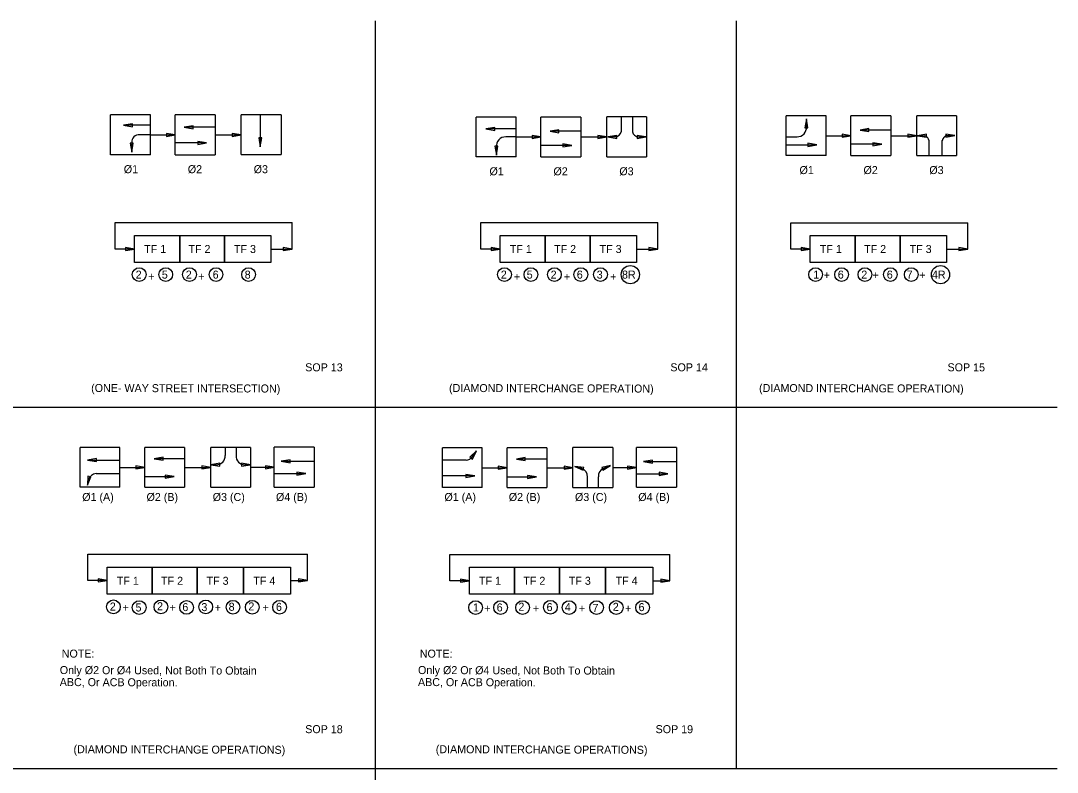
# Model space of a CAD drawing. Extents: x 10027 to 10797, y 10033 to 10528.
# Drawn here: x 10344.3 to 10797.5, y 10199.9 to 10528.4 of the extents above; entities that cross this region are included whole.
import ezdxf

# ---------------------------------------------------------------- set-up
doc = ezdxf.new("R2010")
doc.units = 0
for name, color, linetype in [('AdhocPoint_dp', 7, 'Continuous'), ('Default', 7, 'Continuous'), ('Dimension', 7, 'Continuous'), ('DSIndex', 7, 'Continuous'), ('SupstrConc', 7, 'Continuous')]:
    doc.layers.add(name, color=color, linetype=linetype)

msp = doc.modelspace()

# ---------------------------------------------------------------- linework, layer by layer
at = {"layer": 'AdhocPoint_dp'}
for p, q in [((10499.47, 10033.43), (10499.47, 10528.43)), ((10657.28, 10201.33), (10657.28, 10528.43)), ((10027.5, 10359.54), (10797.5, 10359.54)), ((10797.5, 10201.33), (10027.5, 10201.33))]:
    msp.add_line(p, q, dxfattribs=at)
at = {"layer": 'Default'}
for p, q in [((10401.03, 10487.23), (10383.63, 10487.23)), ((10383.63, 10469.84), (10383.63, 10487.23)), ((10401.03, 10469.84), (10401.03, 10487.23)), ((10411.92, 10469.84), (10411.92, 10487.23)), ((10429.32, 10487.23), (10411.92, 10487.23)), ((10429.32, 10487.23), (10429.32, 10469.84)), ((10440.72, 10469.91), (10440.72, 10487.31)), ((10458.12, 10487.31), (10440.72, 10487.31)), ((10449.05, 10487.02), (10449.05, 10473.3)), ((10458.12, 10487.31), (10458.12, 10469.91)), ((10696.42, 10486.84), (10679.03, 10486.84)), ((10679.03, 10469.45), (10679.03, 10486.84)), ((10696.42, 10469.45), (10696.42, 10486.84)), ((10707.31, 10469.45), (10707.31, 10486.84)), ((10724.71, 10486.84), (10707.31, 10486.84)), ((10724.71, 10486.84), (10724.71, 10469.45)), ((10736.12, 10469.52), (10736.12, 10486.92)), ((10753.51, 10486.92), (10736.12, 10486.92)), ((10753.51, 10486.92), (10753.51, 10469.52)), ((10401.03, 10482.74), (10389.23, 10482.74)), ((10429.16, 10481.87), (10415.83, 10481.87)), ((10560.88, 10486.31), (10543.49, 10486.31)), ((10543.49, 10468.92), (10543.49, 10486.31)), ((10560.88, 10468.92), (10560.88, 10486.31)), ((10571.77, 10468.92), (10571.77, 10486.31)), ((10589.17, 10486.31), (10571.77, 10486.31)), ((10589.17, 10486.31), (10589.17, 10468.92)), ((10600.58, 10468.99), (10600.58, 10486.39)), ((10617.97, 10486.39), (10600.58, 10486.39)), ((10606.81, 10486.39), (10606.81, 10479.91)), ((10611.8, 10486.39), (10611.8, 10479.91)), ((10617.97, 10486.39), (10617.97, 10468.99)), ((10687.83, 10482.09), (10687.83, 10485.54)), ((10401.03, 10478.54), (10396.28, 10478.54)), ((10401.03, 10478.54), (10411.92, 10478.54)), ((10429.32, 10478.54), (10440.72, 10478.54)), ((10560.88, 10481.15), (10547.72, 10481.15)), ((10561.1, 10477.61), (10556.39, 10477.61)), ((10560.88, 10477.61), (10571.77, 10477.61)), ((10589.17, 10480.1), (10575.73, 10480.1)), ((10589.17, 10477.61), (10600.58, 10477.61)), ((10679.03, 10477.71), (10683.73, 10477.71)), ((10696.42, 10478.14), (10707.31, 10478.14)), ((10724.71, 10480.63), (10711.27, 10480.63)), ((10724.71, 10478.14), (10736.12, 10478.14)), ((10392.85, 10475.3), (10392.85, 10470.96)), ((10425.61, 10474.98), (10412.02, 10474.98)), ((10552.3, 10473.24), (10552.3, 10469.68)), ((10585.26, 10473.93), (10571.77, 10473.93)), ((10679.07, 10474.17), (10692.4, 10474.17)), ((10720.8, 10474.46), (10707.31, 10474.46)), ((10741.51, 10469.52), (10741.51, 10476)), ((10747.14, 10469.52), (10747.14, 10476)), ((10401.03, 10469.84), (10383.63, 10469.84)), ((10411.92, 10469.84), (10429.32, 10469.84)), ((10440.72, 10469.91), (10458.12, 10469.91)), ((10560.88, 10468.92), (10543.49, 10468.92)), ((10571.77, 10468.92), (10589.17, 10468.92)), ((10600.58, 10468.99), (10617.97, 10468.99)), ((10696.42, 10469.45), (10679.03, 10469.45)), ((10707.31, 10469.45), (10724.71, 10469.45)), ((10736.12, 10469.52), (10753.51, 10469.52)), ((10385.58, 10440.15), (10462.98, 10440.15)), ((10385.58, 10428.63), (10385.58, 10440.15)), ((10462.98, 10428.63), (10462.98, 10440.15)), ((10545.43, 10440.15), (10622.83, 10440.15)), ((10545.43, 10428.63), (10545.43, 10440.15)), ((10622.83, 10428.63), (10622.83, 10440.15)), ((10680.97, 10440.1), (10758.37, 10440.1)), ((10680.97, 10428.58), (10680.97, 10440.1)), ((10758.37, 10428.58), (10758.37, 10440.1)), ((10394.07, 10428.63), (10385.58, 10428.63)), ((10453.61, 10428.63), (10462.98, 10428.63)), ((10553.93, 10428.63), (10545.43, 10428.63)), ((10613.47, 10428.63), (10622.83, 10428.63)), ((10689.47, 10428.58), (10680.97, 10428.58)), ((10749.01, 10428.58), (10758.37, 10428.58)), ((10387.7, 10341.85), (10370.31, 10341.85)), ((10370.31, 10324.46), (10370.31, 10341.85)), ((10387.7, 10324.46), (10387.7, 10341.85)), ((10398.6, 10324.46), (10398.6, 10341.85)), ((10415.99, 10341.85), (10398.6, 10341.85)), ((10415.99, 10341.85), (10415.99, 10324.46)), ((10427.4, 10324.53), (10427.4, 10341.93)), ((10444.8, 10341.93), (10427.4, 10341.93)), ((10433.7, 10341.95), (10433.7, 10338.36)), ((10438.5, 10341.95), (10438.5, 10338.36)), ((10444.8, 10341.93), (10444.8, 10324.53)), ((10455.2, 10324.58), (10455.2, 10341.98)), ((10472.59, 10341.98), (10455.2, 10341.98)), ((10472.59, 10341.98), (10472.59, 10324.58)), ((10546.08, 10341.72), (10528.68, 10341.72)), ((10528.68, 10324.32), (10528.68, 10341.72)), ((10546.08, 10324.32), (10546.08, 10341.72)), ((10556.97, 10324.32), (10556.97, 10341.72)), ((10574.37, 10341.72), (10556.97, 10341.72)), ((10574.37, 10341.72), (10574.37, 10324.32)), ((10585.77, 10324.4), (10585.77, 10341.79)), ((10603.17, 10341.79), (10585.77, 10341.79)), ((10603.17, 10341.79), (10603.17, 10324.4)), ((10613.57, 10324.45), (10613.57, 10341.85)), ((10630.97, 10341.85), (10613.57, 10341.85)), ((10630.97, 10341.85), (10630.97, 10324.45)), ((10415.97, 10336.95), (10402.63, 10336.95)), ((10541.85, 10337.98), (10543.57, 10340.36)), ((10373.56, 10336.33), (10387.7, 10336.33)), ((10387.7, 10333.15), (10398.6, 10333.15)), ((10415.99, 10333.15), (10427.4, 10333.15)), ((10429.76, 10334.34), (10427.4, 10334.34)), ((10442.43, 10334.34), (10444.8, 10334.34)), ((10444.8, 10333.23), (10455.2, 10333.23)), ((10458.26, 10335.85), (10472.59, 10335.85)), ((10539.02, 10336.25), (10528.68, 10336.25)), ((10546.08, 10333.02), (10556.97, 10333.02)), ((10574.34, 10336.82), (10561.01, 10336.82)), ((10574.37, 10333.02), (10585.77, 10333.02)), ((10603.17, 10333.1), (10613.57, 10333.1)), ((10616.63, 10335.72), (10630.97, 10335.72)), ((10377.36, 10330.54), (10387.7, 10330.54)), ((10398.6, 10329.12), (10411.41, 10329.12)), ((10455.2, 10330.48), (10468.92, 10330.48)), ((10542.82, 10329.46), (10528.68, 10329.46)), ((10556.97, 10328.99), (10569.78, 10328.99)), ((10592.08, 10324.4), (10592.08, 10328.93)), ((10596.87, 10324.4), (10596.87, 10329.08)), ((10613.57, 10330.35), (10627.3, 10330.35)), ((10387.7, 10324.46), (10370.31, 10324.46)), ((10398.6, 10324.46), (10415.99, 10324.46)), ((10427.4, 10324.53), (10444.8, 10324.53)), ((10455.2, 10324.58), (10472.59, 10324.58)), ((10546.08, 10324.32), (10528.68, 10324.32)), ((10556.97, 10324.32), (10574.37, 10324.32)), ((10585.77, 10324.4), (10603.17, 10324.4)), ((10613.57, 10324.45), (10630.97, 10324.45)), ((10373.61, 10295.24), (10469.67, 10295.24)), ((10373.61, 10283.72), (10373.61, 10295.24)), ((10469.67, 10283.72), (10469.67, 10295.24)), ((10531.98, 10295.11), (10628.05, 10295.11)), ((10531.98, 10283.59), (10531.98, 10295.11)), ((10628.05, 10283.59), (10628.05, 10295.11)), ((10382.1, 10283.72), (10373.61, 10283.72)), ((10462.24, 10283.72), (10469.67, 10283.72)), ((10540.48, 10283.59), (10531.98, 10283.59)), ((10620.61, 10283.59), (10628.05, 10283.59))]:
    msp.add_line(p, q, dxfattribs=at)
for centre in [(10384.84, 10272.19), (10396.12, 10271.87), (10405.6, 10272.14), (10416.85, 10271.95), (10425.22, 10272.17), (10437.13, 10272.04), (10445.53, 10272.03), (10457.49, 10272.03), (10543.17, 10271.86), (10554.12, 10271.86), (10563.74, 10271.86), (10575.88, 10272.02), (10584.09, 10271.86), (10596.12, 10271.86), (10604.69, 10271.9), (10616.18, 10271.86)]:
    msp.add_circle(centre, 3, dxfattribs=at)
for centre, radius, start, end in [((10683.87, 10481.69), 3.98, 268.0112, 5.8153), ((10396.06, 10475.33), 3.21, 86.1951, 181.3491), ((10556.25, 10473.64), 3.98, 88.0112, 185.8153), ((10603.91, 10480.57), 2.97, 280.5531, 347.2625), ((10614.7, 10480.57), 2.97, 192.7375, 264.4319), ((10738.62, 10475.34), 2.97, 12.7375, 69.8753), ((10750.03, 10475.34), 2.97, 104.651, 167.2625), ((10429.93, 10338.12), 3.78, 267.4678, 3.6758), ((10442.27, 10338.12), 3.78, 176.3242, 272.5322), ((10538.63, 10340.06), 3.83, 275.8582, 327.0511), ((10588.31, 10329.17), 3.78, 356.3242, 69.2644), ((10600.64, 10329.32), 3.78, 116.8576, 183.6758), ((10377.75, 10326.73), 3.83, 95.8582, 167.523)]:
    msp.add_arc(centre, radius, start, end, dxfattribs=at)
at = {"layer": 'Dimension'}
for p, q in [((10604.45, 10477.64), (10600.99, 10477.64)), ((10614.41, 10477.61), (10617.66, 10477.61)), ((10736.42, 10478.13), (10739.64, 10478.13)), ((10749.28, 10478.22), (10752.66, 10478.22)), ((10589.64, 10332.71), (10586.6, 10333.49)), ((10598.93, 10332.69), (10602.22, 10333.96)), ((10374.01, 10327.56), (10373.59, 10325.32))]:
    msp.add_line(p, q, dxfattribs=at)
for centre, radius in [((10396.12, 10417.44), 3), ((10407.75, 10417.44), 3), ((10418.12, 10417.44), 3), ((10429.7, 10417.44), 3), ((10443.94, 10417.44), 3), ((10555.82, 10417.44), 3), ((10567.36, 10417.44), 3), ((10577.64, 10417.44), 3), ((10589.2, 10417.44), 3), ((10597.79, 10417.44), 3), ((10610.85, 10417.44), 3.99), ((10691.84, 10417.44), 3), ((10703.21, 10417.44), 3), ((10713.42, 10417.44), 3), ((10724.52, 10417.44), 3), ((10733.69, 10417.44), 3), ((10746.46, 10417.44), 3.99)]:
    msp.add_circle(centre, radius, dxfattribs=at)
at = {"layer": 'DSIndex'}
for points in [[(10394.07, 10434.51), (10413.82, 10434.51), (10413.82, 10422.75), (10394.07, 10422.75)], [(10413.82, 10434.51), (10433.42, 10434.51), (10433.42, 10422.75), (10413.82, 10422.75)], [(10433.42, 10434.51), (10453.61, 10434.51), (10453.61, 10422.75), (10433.42, 10422.75)], [(10553.93, 10434.51), (10573.67, 10434.51), (10573.67, 10422.75), (10553.93, 10422.75)], [(10573.67, 10434.51), (10593.28, 10434.51), (10593.28, 10422.75), (10573.67, 10422.75)], [(10593.28, 10434.51), (10613.47, 10434.51), (10613.47, 10422.75), (10593.28, 10422.75)], [(10689.47, 10434.51), (10709.21, 10434.51), (10709.21, 10422.75), (10689.47, 10422.75)], [(10709.21, 10434.51), (10728.82, 10434.51), (10728.82, 10422.75), (10709.21, 10422.75)], [(10728.82, 10434.51), (10749.01, 10434.51), (10749.01, 10422.75), (10728.82, 10422.75)], [(10382.1, 10289.47), (10401.85, 10289.47), (10401.85, 10277.71), (10382.1, 10277.71)], [(10401.85, 10289.47), (10421.45, 10289.47), (10421.45, 10277.71), (10401.85, 10277.71)], [(10421.45, 10289.47), (10441.65, 10289.47), (10441.65, 10277.71), (10421.45, 10277.71)], [(10441.65, 10289.47), (10462.24, 10289.47), (10462.24, 10277.71), (10441.65, 10277.71)], [(10540.48, 10289.47), (10560.22, 10289.47), (10560.22, 10277.71), (10540.48, 10277.71)], [(10560.22, 10289.47), (10579.83, 10289.47), (10579.83, 10277.71), (10560.22, 10277.71)], [(10579.83, 10289.47), (10600.02, 10289.47), (10600.02, 10277.71), (10579.83, 10277.71)], [(10600.02, 10289.47), (10620.61, 10289.47), (10620.61, 10277.71), (10600.02, 10277.71)]]:
    msp.add_lwpolyline(points, close=True, dxfattribs=at)
at = {"layer": 'SupstrConc'}
for points in [[(10389.23, 10482.74), (10393.13, 10482.08), (10393.13, 10483.4)], [(10415.83, 10481.87), (10419.74, 10481.21), (10419.74, 10482.53)], [(10687.83, 10485.54), (10687.17, 10481.64), (10688.49, 10481.64)], [(10411.92, 10478.54), (10408.01, 10479.2), (10408.01, 10477.88)], [(10440.72, 10478.54), (10436.82, 10479.2), (10436.82, 10477.88)], [(10547.72, 10481.15), (10551.63, 10480.49), (10551.63, 10481.82)], [(10571.77, 10477.61), (10567.87, 10478.28), (10567.87, 10476.95)], [(10575.73, 10480.1), (10579.64, 10479.44), (10579.64, 10480.76)], [(10600.58, 10477.61), (10596.67, 10478.28), (10596.67, 10476.95)], [(10600.99, 10477.64), (10604.9, 10476.98), (10604.9, 10478.31)], [(10617.66, 10477.61), (10613.76, 10478.27), (10613.76, 10476.95)], [(10707.31, 10478.14), (10703.41, 10478.81), (10703.41, 10477.48)], [(10711.27, 10480.63), (10715.18, 10479.97), (10715.18, 10481.29)], [(10736.12, 10478.14), (10732.21, 10478.81), (10732.21, 10477.48)], [(10736.42, 10478.13), (10740.32, 10477.47), (10740.32, 10478.79)], [(10752.66, 10478.22), (10748.76, 10478.88), (10748.76, 10477.56)], [(10392.85, 10470.96), (10393.51, 10474.86), (10392.19, 10474.86)], [(10425.61, 10474.98), (10421.7, 10475.64), (10421.7, 10474.32)], [(10449.05, 10473.3), (10449.71, 10477.2), (10448.39, 10477.2)], [(10552.3, 10469.68), (10552.96, 10473.58), (10551.63, 10473.58)], [(10585.26, 10473.93), (10581.35, 10474.59), (10581.35, 10473.27)], [(10692.4, 10474.17), (10688.5, 10474.84), (10688.5, 10473.51)], [(10720.8, 10474.46), (10716.89, 10475.12), (10716.89, 10473.8)], [(10394.07, 10428.63), (10390.17, 10429.29), (10390.17, 10427.97)], [(10462.98, 10428.63), (10459.07, 10429.29), (10459.07, 10427.97)], [(10553.93, 10428.63), (10550.02, 10429.29), (10550.02, 10427.97)], [(10622.83, 10428.63), (10618.93, 10429.29), (10618.93, 10427.97)], [(10689.47, 10428.58), (10685.56, 10429.24), (10685.56, 10427.92)], [(10758.37, 10428.58), (10754.47, 10429.24), (10754.47, 10427.92)], [(10373.56, 10336.33), (10377.46, 10335.67), (10377.46, 10337)], [(10402.63, 10336.95), (10406.54, 10336.29), (10406.54, 10337.61)], [(10543.57, 10340.36), (10540.74, 10337.58), (10541.81, 10336.81)], [(10561.01, 10336.82), (10564.91, 10336.15), (10564.91, 10337.48)], [(10398.6, 10333.15), (10394.69, 10333.82), (10394.69, 10332.49)], [(10427.4, 10333.15), (10423.49, 10333.82), (10423.49, 10332.49)], [(10427.4, 10334.34), (10431.31, 10333.68), (10431.31, 10335.01)], [(10444.8, 10334.34), (10440.89, 10335.01), (10440.89, 10333.68)], [(10455.2, 10333.23), (10451.29, 10333.89), (10451.29, 10332.57)], [(10458.26, 10335.85), (10462.16, 10335.19), (10462.16, 10336.51)], [(10556.97, 10333.02), (10553.07, 10333.68), (10553.07, 10332.36)], [(10585.77, 10333.02), (10581.87, 10333.68), (10581.87, 10332.36)], [(10586.6, 10333.49), (10590.22, 10331.88), (10590.55, 10333.16)], [(10602.22, 10333.96), (10598.34, 10333.17), (10598.82, 10331.94)], [(10613.57, 10333.1), (10609.67, 10333.76), (10609.67, 10332.44)], [(10616.63, 10335.72), (10620.54, 10335.06), (10620.54, 10336.38)], [(10373.59, 10325.32), (10374.96, 10329.04), (10373.66, 10329.28)], [(10411.41, 10329.12), (10407.51, 10329.78), (10407.51, 10328.46)], [(10468.92, 10330.48), (10465.02, 10331.14), (10465.02, 10329.82)], [(10542.82, 10329.46), (10538.92, 10330.12), (10538.92, 10328.8)], [(10569.78, 10328.99), (10565.88, 10329.65), (10565.88, 10328.33)], [(10627.3, 10330.35), (10623.39, 10331.01), (10623.39, 10329.68)], [(10382.1, 10283.72), (10378.2, 10284.38), (10378.2, 10283.06)], [(10469.67, 10283.72), (10465.77, 10284.38), (10465.77, 10283.06)], [(10540.48, 10283.59), (10536.57, 10284.25), (10536.57, 10282.93)], [(10628.05, 10283.59), (10624.14, 10284.25), (10624.14, 10282.93)]]:
    msp.add_lwpolyline(points, close=True, dxfattribs=at)

# ---------------------------------------------------------------- texts
at = {"layer": 'Dimension'}
for s, p in [('Ø1', (10389.4, 10461.78)), ('Ø2', (10417.38, 10461.78)), ('Ø3', (10446.18, 10461.78)), ('Ø1', (10549.26, 10460.86)), ('Ø2', (10577.23, 10460.86)), ('Ø3', (10606.03, 10460.86)), ('Ø1', (10684.8, 10461.39)), ('Ø2', (10712.77, 10461.39)), ('Ø3', (10741.57, 10461.39)), ('TF 1', (10398.29, 10426.88)), ('TF 2', (10417.65, 10426.88)), ('TF 3', (10437.55, 10426.88)), ('TF 1', (10558.15, 10426.88)), ('TF 2', (10577.51, 10426.88)), ('TF 3', (10597.4, 10426.88)), ('TF 1', (10693.69, 10426.88)), ('TF 2', (10713.05, 10426.88)), ('TF 3', (10732.94, 10426.88)), ('8R', (10607.2, 10415.7)), ('+', (10695.37, 10415.54)), ('+', (10716.71, 10415.54)), ('+', (10737.11, 10415.54)), ('4R', (10742.69, 10415.69)), ('+', (10400.06, 10414.85)), ('+', (10421.89, 10414.85)), ('+', (10559.89, 10414.77)), ('+', (10581.77, 10414.77)), ('+', (10602, 10414.77)), ('Ø1 (A)', (10371.21, 10318.47)), ('Ø2 (B)', (10399.33, 10318.47)), ('Ø3 (C)', (10428.26, 10318.47)), ('Ø4 (B)', (10455.93, 10318.47)), ('Ø1 (A)', (10529.58, 10318.47)), ('Ø2 (B)', (10557.7, 10318.47)), ('Ø3 (C)', (10586.64, 10318.47)), ('Ø4 (B)', (10614.31, 10318.47)), ('TF 1', (10386.32, 10281.84)), ('TF 2', (10405.68, 10281.84)), ('TF 3', (10425.58, 10281.84)), ('TF 4', (10446.04, 10281.84)), ('TF 1', (10544.7, 10281.84)), ('TF 2', (10564.06, 10281.84)), ('TF 3', (10583.95, 10281.84)), ('TF 4', (10604.42, 10281.84)), ('+', (10388.81, 10270.12)), ('+', (10409.43, 10270.12)), ('+', (10429.12, 10270.12)), ('+', (10450.02, 10270.12)), ('+', (10546.96, 10269.73)), ('+', (10568.21, 10269.73)), ('+', (10588.36, 10269.73)), ('+', (10608.51, 10269.73)), ('NOTE:', (10362.25, 10250))]:
    msp.add_text(s, height=3.5, dxfattribs=at).set_placement(p)
for s, rotation, p in [('2', 359.6943, (10394.57, 10415.7)), ('5', 359.6943, (10406, 10415.7)), ('2', 359.6943, (10416.49, 10415.7)), ('6', 359.6943, (10428.23, 10415.7)), ('8', 359.6943, (10442.24, 10415.7)), ('2', 359.6943, (10554.22, 10415.7)), ('5', 359.6943, (10565.54, 10415.7)), ('2', 359.6943, (10575.99, 10415.7)), ('6', 359.6943, (10587.43, 10415.7)), ('3', 359.6943, (10596.14, 10415.7)), ('1', 359.6943, (10690.83, 10415.69)), ('6', 359.6943, (10701.53, 10415.7)), ('2', 359.6943, (10711.79, 10415.7)), ('6', 359.6943, (10722.96, 10415.7)), ('7', 359.6943, (10731.63, 10415.7)), ('SOP 13', 359.8217, (10468.7, 10375.18)), ('SOP 14', 359.8217, (10628.34, 10375.18)), ('SOP 15', 359.8217, (10749.52, 10375.18)), (' (ONE- WAY STREET INTERSECTION)', 359.8217, (10373.81, 10366.14)), ('(DIAMOND INTERCHANGE OPERATION)', 359.8217, (10531.58, 10366.13)), ('(DIAMOND INTERCHANGE OPERATION)', 359.8217, (10667.12, 10366.13)), ('2', 359.6943, (10383.27, 10270.58)), ('5', 359.6943, (10394.5, 10270.18)), ('2', 359.6943, (10403.91, 10270.72)), ('6', 359.6943, (10414.98, 10270.34)), ('3', 359.6943, (10423.3, 10270.34)), ('8', 359.6943, (10435.22, 10270.49)), ('2', 359.6943, (10443.84, 10270.64)), ('6', 359.6943, (10455.9, 10270.44)), ('1', 359.6943, (10542.03, 10270.19)), ('6', 359.6943, (10552.41, 10270.2)), ('2', 359.6943, (10561.91, 10270.5)), ('6', 359.6943, (10574.21, 10270.35)), ('4', 359.6943, (10582.21, 10270.35)), ('7', 359.6943, (10594.3, 10270)), ('2', 359.6943, (10603.17, 10270.46)), ('6', 359.6943, (10614.43, 10270.33)), ('NOTE:', 359.8217, (10518.79, 10250)), ('Only Ø2 Or Ø4 Used, Not Both To Obtain', 359.8217, (10361.4, 10242.82)), ('Only Ø2 Or Ø4 Used, Not Both To Obtain', 359.8217, (10518.02, 10242.82)), ('ABC, Or ACB Operation.', 359.8217, (10361.38, 10237.57)), ('ABC, Or ACB Operation.', 359.8217, (10518, 10237.57)), ('SOP 18', 359.8217, (10468.7, 10216.99)), ('SOP 19', 359.8217, (10621.88, 10216.99)), ('(DIAMOND INTERCHANGE OPERATIONS)', 359.8217, (10367.4, 10208.22)), ('(DIAMOND INTERCHANGE OPERATIONS)', 359.8217, (10525.78, 10208.22))]:
    msp.add_text(s, height=3.5, rotation=rotation, dxfattribs=at).set_placement(p)

doc.saveas('drawing.dxf')
